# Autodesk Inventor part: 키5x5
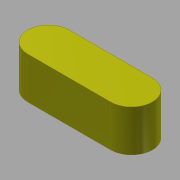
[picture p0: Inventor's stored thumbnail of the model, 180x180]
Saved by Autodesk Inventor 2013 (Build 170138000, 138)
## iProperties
Created: 2011-04
Part Number: 키5x5
Document SubType Name: Modeling
Designer: pww
Density: 7.86 g/cm^3
Material: 강철, 연강
Author: pww
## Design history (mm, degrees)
sketch "스케치1"
  geometry: L1 (-5, -2.5)-(5, -2.5); L2 (5, 2.5)-(-5, 2.5); A1 r 2.5 centre (-5, 0) between (-5, 2.5) and (-5, -2.5); A2 r 2.5 centre (5, 0) between (5, -2.5) and (5, 2.5); 1 further point
  constraints: 4 end point, 4 point on circle, 2 centre point
extrude "돌출1" new body sketch "스케치1" distance "d0" = 5; taper "d1" = 0 deg
node "솔리드1"
